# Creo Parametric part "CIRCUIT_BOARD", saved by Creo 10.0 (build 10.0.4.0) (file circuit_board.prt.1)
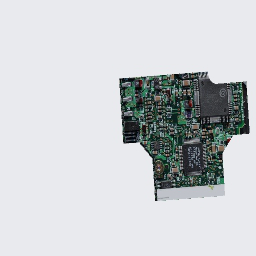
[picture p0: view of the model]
Units: millimeter Kilogram Sec (mmKs); MM, KILOGRAM, SECS

Created from: XX_SOLID_PART_MMKS_NEW_ABS.PRT

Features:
  1. datum plane "RIGHT"
  2. datum plane "TOP"
  3. datum plane "FRONT"
  4. coordinate system
  5. sketch "Sketch 1"
  6. extrusion "Extrude 1"

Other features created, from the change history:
  group "COPIED_GROUP"

Surfaces: 14 plane, 1 cylinder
